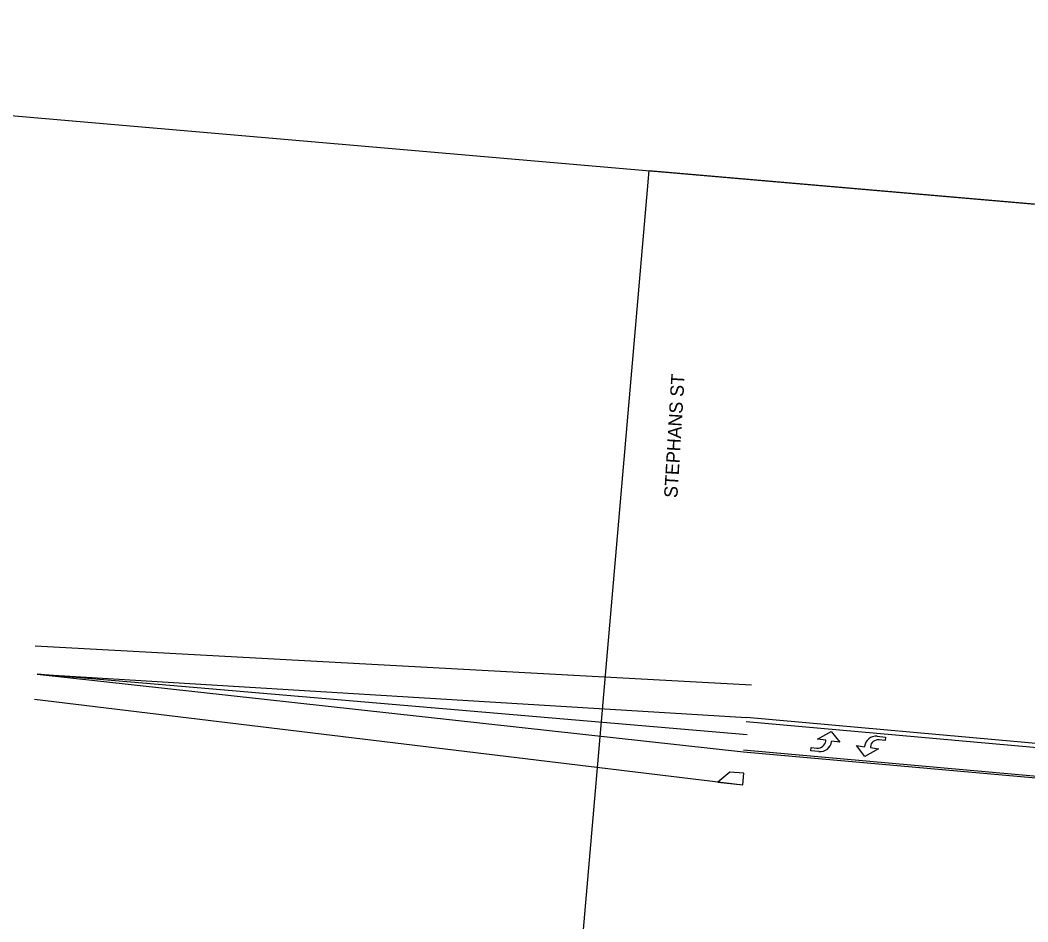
# Model space of a CAD drawing. Extents: x 20499978 to 20505524, y 7953342 to 7954320.
# Drawn here: x 20501469.8 to 20501922.3, y 7953807.9 to 7954212.7 of the extents above; entities that cross this region are included whole.
import ezdxf

# ---------------------------------------------------------------- set-up
doc = ezdxf.new("R2010")
doc.units = 0
for name, color, linetype in [('Curb', 7, 'Continuous'), ('EdgePaved', 7, 'Continuous'), ('Entrance', 7, 'Continuous'), ('Text', 7, 'Continuous'), ('UtilitiesBelowGround', 7, 'Continuous')]:
    doc.layers.add(name, color=color, linetype=linetype)

msp = doc.modelspace()

# ---------------------------------------------------------------- linework, layer by layer
at = {"layer": 'Curb'}
for p, q in [((20501476.46884623, 7953931.794882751), (20501798.255868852, 7953914.214779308)), ((20501796.24923437, 7953891.804437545), (20501477.410398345, 7953919.0403814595)), ((20501477.410398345, 7953919.0403814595), (20501795.922847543, 7953899.614667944)), ((20501477.410398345, 7953919.0403814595), (20501794.540503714, 7953884.176432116)), ((20501476.264044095, 7953907.892411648), (20501794.24259989, 7953869.39409578))]:
    msp.add_line(p, q, dxfattribs=at)
msp.add_lwpolyline([(20501788.44306221, 7953875.066333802), (20501783.09322418, 7953870.558418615), (20501794.24259989, 7953869.394095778), (20501794.708161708, 7953874.593547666)], close=True, dxfattribs=at)
at = {"layer": 'EdgePaved'}
for p, q in [((20502203.260144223, 7953863.141575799), (20501795.92284754, 7953899.614667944)), ((20501794.540503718, 7953884.176432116), (20502218.73298789, 7953846.234943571))]:
    msp.add_line(p, q, dxfattribs=at)
for points in [[(20502362.114028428, 7953847.378971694), (20502203.09200555, 7953861.232306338), (20501795.75191305, 7953897.705645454)], [(20502361.001597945, 7953834.608532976), (20502201.961460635, 7953848.448849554), (20501794.60739132, 7953884.923443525)]]:
    msp.add_lwpolyline(points, dxfattribs=at)
at = {"layer": 'Entrance'}
for p, q in [((20501831.49094295, 7953889.037927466), (20501831.51821212, 7953889.351279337)), ((20501834.12528153, 7953888.992849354), (20501834.109374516, 7953888.810060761)), ((20501848.945249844, 7953886.461360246), (20501848.96115686, 7953886.644148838)), ((20501851.579588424, 7953886.416282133), (20501851.552319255, 7953886.102930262))]:
    msp.add_line(p, q, dxfattribs=at)
for points in [[(20501831.51821212, 7953889.351279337), (20501827.868314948, 7953889.853081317), (20501833.97427389, 7953893.320898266)], [(20501831.51821212, 7953889.351279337), (20501827.868314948, 7953889.853081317), (20501833.97427389, 7953893.320898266)], [(20501833.97427389, 7953893.320898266), (20501837.775178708, 7953888.491047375), (20501834.12528153, 7953888.992849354)], [(20501833.97427389, 7953893.320898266), (20501837.775178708, 7953888.491047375), (20501834.12528153, 7953888.992849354)], [(20501831.490942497, 7953889.037922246), (20501831.51821212, 7953889.351279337)], [(20501834.12528153, 7953888.992849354), (20501834.109374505, 7953888.810060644)], [(20501854.62978187, 7953891.149820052), (20501858.29558606, 7953890.830806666), (20501858.166057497, 7953889.342385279), (20501855.54762593, 7953889.5702519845)], [(20501854.62978187, 7953891.149820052), (20501858.29558606, 7953890.830806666), (20501858.166057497, 7953889.342385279), (20501855.54762593, 7953889.5702519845)], [(20501828.44074951, 7953884.304389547), (20501824.774945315, 7953884.623402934), (20501824.904473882, 7953886.111824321), (20501827.52290545, 7953885.883957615)], [(20501828.44074951, 7953884.304389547), (20501824.774945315, 7953884.623402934), (20501824.904473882, 7953886.111824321), (20501827.52290545, 7953885.883957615)], [(20501849.096257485, 7953882.133311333), (20501845.295352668, 7953886.963162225), (20501848.945249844, 7953886.461360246)], [(20501849.096257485, 7953882.133311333), (20501845.295352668, 7953886.963162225), (20501848.945249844, 7953886.461360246)], [(20501848.945249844, 7953886.461360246), (20501848.961156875, 7953886.644148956)], [(20501851.552319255, 7953886.102930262), (20501855.202216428, 7953885.601128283), (20501849.096257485, 7953882.133311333)], [(20501851.552319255, 7953886.102930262), (20501855.202216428, 7953885.601128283), (20501849.096257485, 7953882.133311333)], [(20501851.57958888, 7953886.416287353), (20501851.552319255, 7953886.102930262)]]:
    msp.add_lwpolyline(points, dxfattribs=at)
for centre, major_axis, ratio, start_param in [((20501827.825138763, 7953889.356940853), (-3.665804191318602, 0.31901338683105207), 0.9474000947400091, 1.5707963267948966), ((20501827.825138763, 7953889.356940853), (-3.665804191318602, 0.31901338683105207), 0.9474000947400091, 1.5707963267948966), ((20501828.872511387, 7953889.265794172), (-5.236863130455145, 0.45573340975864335), 0.9474000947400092, 1.5707963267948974), ((20501828.872511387, 7953889.265794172), (-5.236863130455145, 0.45573340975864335), 0.9474000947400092, 1.5707963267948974), ((20501854.19801999, 7953886.188415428), (5.236863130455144, -0.4557334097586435), 0.9474000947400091, 1.5707963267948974), ((20501854.19801999, 7953886.188415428), (5.236863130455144, -0.4557334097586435), 0.9474000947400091, 1.5707963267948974), ((20501855.245392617, 7953886.097268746), (3.6658041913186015, -0.3190133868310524), 0.947400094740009, 1.5707963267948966), ((20501855.245392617, 7953886.097268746), (3.6658041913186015, -0.3190133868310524), 0.947400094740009, 1.5707963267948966)]:
    msp.add_ellipse(centre, major_axis=major_axis, ratio=ratio, start_param=start_param, end_param=3.141592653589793, dxfattribs=at)
at = {"layer": 'Text'}
for points in [[(20500970.870100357, 7954212.672987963), (20502532.504970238, 7954077.5622130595), (20502489.40637099, 7953579.420777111), (20500927.771501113, 7953714.531552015)], [(20501752.189117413, 7954145.122862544), (20503313.82398729, 7954010.012087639), (20503270.725388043, 7953511.870651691), (20501709.090518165, 7953646.981426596)]]:
    msp.add_lwpolyline(points, close=True, dxfattribs=at)

# ---------------------------------------------------------------- texts
at = {"layer": 'UtilitiesBelowGround'}
msp.add_text('STEPHANS ST', height=5.999999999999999, rotation=86.57159921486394, dxfattribs=at).set_placement((20501764.876119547, 7953998.046350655))

doc.saveas('drawing.dxf')
